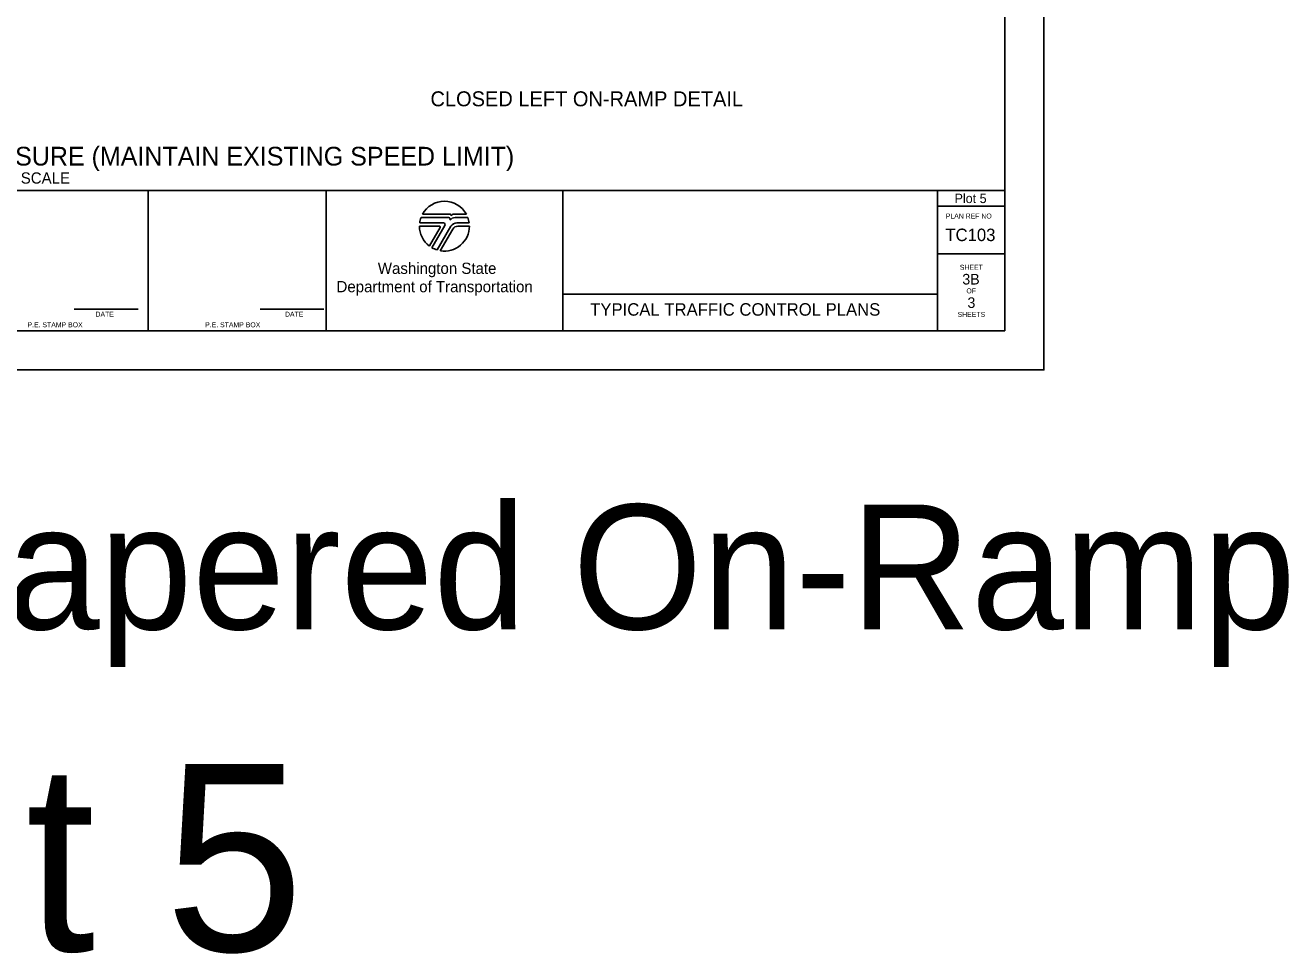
# Model space of a CAD drawing. Extents: x 99999 to 100116, y 99995 to 100013.
# Drawn here: x 100087.9 to 100098.02, y 99995.01 to 100002.45 of the extents above; entities that cross this region are included whole.
import ezdxf

# ---------------------------------------------------------------- set-up
doc = ezdxf.new("R2010")
doc.units = 0
for name, color, linetype in [('SH_DE_DetailHeading1Text', 7, 'Continuous'), ('SH_DE_DetailHeading2Text', 7, 'Continuous'), ('SH_GI_PlotLimits', 7, 'Continuous'), ('SH_GI_SheetBorder', 7, 'Continuous'), ('SH_GI_SheetLocationText', 7, 'Continuous'), ('SH_GI_SheetTextInCells', 7, 'Continuous'), ('SH_GI_TitleBlockText', 7, 'Continuous'), ('SH_GI_WSDOTLogo', 7, 'Continuous')]:
    doc.layers.add(name, color=color, linetype=linetype)

msp = doc.modelspace()

# ---------------------------------------------------------------- linework, layer by layer
at = {"layer": 'SH_GI_PlotLimits'}
msp.add_lwpolyline([(100079.062, 99999.687), (100096.062, 99999.687), (100096.062, 100010.687), (100079.062, 100010.687)], close=True, dxfattribs=at)
at = {"layer": 'SH_GI_SheetBorder'}
for p, q in [((100095.75, 100010.375), (100095.75, 100000)), ((100080, 100001.126), (100095.75, 100001.126)), ((100088.883, 100000), (100088.883, 100001.126)), ((100090.309, 100001.126), (100090.309, 100000)), ((100092.205, 100001.126), (100092.205, 100000)), ((100095.208, 100001.126), (100095.208, 100000)), ((100095.208, 100001.001), (100095.75, 100001.001)), ((100095.208, 100000.618), (100095.75, 100000.618)), ((100092.205, 100000.295), (100095.208, 100000.295)), ((100088.29, 100000.173), (100088.802, 100000.173)), ((100089.78, 100000.173), (100090.291, 100000.173)), ((100080, 100000), (100095.75, 100000))]:
    msp.add_line(p, q, dxfattribs=at)
at = {"layer": 'SH_GI_WSDOTLogo'}
for p, q in [((100091.059, 100000.866), (100091.25, 100000.866)), ((100091.289, 100000.909), (100091.07, 100000.909)), ((100091.303, 100000.935), (100091.081, 100000.935)), ((100091.433, 100000.935), (100091.335, 100000.935)), ((100091.445, 100000.909), (100091.343, 100000.909)), ((100091.343, 100000.909), (100091.343, 100000.909)), ((100091.356, 100000.866), (100091.456, 100000.866)), ((100091.057, 100000.84), (100091.215, 100000.84)), ((100091.222, 100000.828), (100091.136, 100000.681)), ((100091.261, 100000.846), (100091.157, 100000.667)), ((100091.199, 100000.649), (100091.309, 100000.839)), ((100091.224, 100000.643), (100091.324, 100000.816)), ((100091.365, 100000.839), (100091.457, 100000.839))]:
    msp.add_line(p, q, dxfattribs=at)
for centre, radius, start, end in [((100091.257, 100000.84), 0.2, 28.4787, 151.532), ((100091.257, 100000.84), 0.2, 159.696, 172.5057), ((100091.25, 100000.853), 0.0131, 329.7683, 90), ((100091.289, 100000.895), 0.0148, 327.8418, 89.9985), ((100091.343, 100000.861), 0.0484, 89.9953, 147.8238), ((100091.303, 100000.926), 0.00903, 329.8742, 90.0033), ((100091.356, 100000.812), 0.0542, 90, 149.9974), ((100091.335, 100000.907), 0.0287, 90.0072, 148.1676), ((100091.257, 100000.84), 0.2, 7.4943, 20.2941), ((100091.257, 100000.84), 0.2, 179.9986, 232.8433), ((100091.215, 100000.832), 0.0082, 329.7436, 90), ((100091.257, 100000.84), 0.2, 260.5455, 359.8086), ((100091.365, 100000.792), 0.0476, 90, 150.0543), ((100091.257, 100000.84), 0.2, 239.7929, 253.0448)]:
    msp.add_arc(centre, radius, start, end, dxfattribs=at)

# ---------------------------------------------------------------- texts
at = {"layer": 'SH_DE_DetailHeading1Text'}
for s, height, p in [('FREEWAY (2+ LANES): SINGLE LEFT LANE CLOSURE (MAINTAIN EXISTING SPEED LIMIT)', 0.15, (100083.251, 100001.326)), ('NOT TO SCALE', 0.09, (100087.373, 100001.181))]:
    msp.add_text(s, height=height, rotation=360, dxfattribs=at).set_placement(p)
at = {"layer": 'SH_DE_DetailHeading2Text'}
msp.add_text('CLOSED LEFT ON-RAMP DETAIL', height=0.12, rotation=360, dxfattribs=at).set_placement((100091.145, 100001.801))
at = {"layer": 'SH_GI_SheetBorder'}
msp.add_text('PLAN REF NO', height=0.04003, dxfattribs=at).set_placement((100095.275, 100000.901))
at = {"layer": 'SH_GI_SheetLocationText'}
for s, height, p in [('Plot 5', 0.075, (100095.346, 100001.025)), ('Left Ramps: Tapered On-Ramp', 1, (100079.351, 99997.607)), ('Plot 5', 1.5, (100085.001, 99995.027))]:
    msp.add_text(s, height=height, dxfattribs=at).set_placement(p)
at = {"layer": 'SH_GI_SheetTextInCells'}
for s, height, p in [('Washington State', 0.09007, (100090.723, 100000.457)), ('SHEET', 0.04, (100095.388, 100000.49)), ('Department of Transportation', 0.09007, (100090.392, 100000.31)), ('OF', 0.04, (100095.441, 100000.301)), ('DATE', 0.04, (100088.46, 100000.114)), ('DATE', 0.04, (100089.979, 100000.114)), ('SHEETS', 0.04, (100095.37, 100000.112)), ('P.E. STAMP BOX', 0.04003, (100087.915, 100000.029)), ('P.E. STAMP BOX', 0.04003, (100089.339, 100000.029))]:
    msp.add_text(s, height=height, dxfattribs=at).set_placement(p)
at = {"layer": 'SH_GI_TitleBlockText'}
for s, height, p in [('TC103', 0.1, (100095.272, 100000.72)), ('3B', 0.085, (100095.408, 100000.372)), ('3', 0.085, (100095.449, 100000.184)), ('TYPICAL TRAFFIC CONTROL PLANS', 0.1, (100092.425, 100000.122))]:
    msp.add_text(s, height=height, dxfattribs=at).set_placement(p)

doc.saveas('drawing.dxf')
